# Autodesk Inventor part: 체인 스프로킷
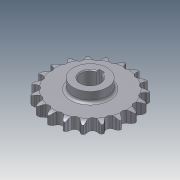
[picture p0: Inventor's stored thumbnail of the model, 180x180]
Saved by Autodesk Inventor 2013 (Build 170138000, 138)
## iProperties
Created: 2013-01
Part Number: 체인 스프로킷
Material: 강
Document SubType Name: Modeling
Designer: KYOUNG IL JANG
Density: 1 g/cm^3
CustomPartVersion: 1
Company: 한국ATC센터
Author: KYOUNG IL JANG
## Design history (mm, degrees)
sketch "이론적 톱니 프로파일"
  geometry: L1 (0, 0)-(0, 45.567); L2 (0, 0)-(14.795, 43.098); L3 (0, 45.567)-(14.795, 43.098); L4 (0, 45.567)-(5.661, 50.015); L5 (5.661, 50.015)-(-5.141, 45.406); L6 (-12.428, 43.493)-(-5.573, 46.417); L7 (-5.141, 45.406)-(-5.573, 46.417); L8 (5.573, 46.417)-(5.141, 45.406); L9 (0, 0)-(8.138, 48.771); A1 r 45.567 centre (0, 0) between (0, 45.567) and (14.795, 43.098); A2 r 49.445 centre (0, 0) between (7.302, 48.903) and (-7.302, 48.903); A3 r 4.545 centre (0, 45.567) between (-3.574, 42.758) and (3.574, 42.758); A4 r 7.453 centre (12.428, 43.493) between (7.302, 48.903) and (5.573, 46.417); A5 r 7.453 centre (-12.428, 43.493) between (-5.573, 46.417) and (-7.302, 48.903); A6 r 11.745 centre (5.661, 50.015) between (-5.141, 45.406) and (-3.574, 42.758); A7 r 11.745 centre (-5.661, 50.015) between (3.574, 42.758) and (5.141, 45.406); 2 further points
  constraints: 18 end point, 15 point on circle, 7 centre point, 3 coincident, 3 point on line, 3 symmetric about line, 3 tangent, 1 equal radius, 1 midpoint, 1 parallel, 1 vertical, 1 other
  dimensions: "d0" = 91.13301 diameter of A1 (computed from da_p, da_z); "d2" = 18.9474 deg angle of L2 L1 (computed from da_z); "d3" = 4.545 radius of A3 (= 0.5 x da_Dr + da_SC); "d10" = 128.158 deg angle of L4 L1 (computed from da_z); "d11" = 15.0526 deg angle of L5 L4 (computed from da_z); "d12" = 7.2 distance of L3.start L4.end (= 0.8 x da_Dr); "d13" = 11.745 distance of L4.end L5.end (= 1.3 x da_Dr + da_SC); "d14" = 12.6 distance of A4.centre L1.end (= 1.4 x da_Dr); "d23" = 4.5 distance from line of L9.end L3 (= da_Ha)
sketch "톱니 프로파일"
  geometry: L1 (0, 0)-(0, 45.567); L2 (0, 45.567)-(4.203, 43.837); L3 (0, 45.567)-(-4.203, 43.837); A1 r 4.545 centre (0, 45.567) between (-4.203, 43.837) and (4.203, 43.837); A2 r 22.68 centre (25.176, 35.206) between (7.12, 48.93) and (4.203, 43.837); A3 r 22.68 centre (-25.176, 35.206) between (-4.203, 43.837) and (-7.12, 48.93); A4 r 49.445 centre (0, 0) between (-7.12, 48.93) and (7.12, 48.93) reference; 1 further point
  constraints: 9 point on circle, 6 end point, 3 centre point, 2 tangent, 1 coincident, 1 equal radius, 1 vertical, 1 other
  dimensions: "d44" = 135.263 deg angle of L3 L2 (= da_Alfa); "d45" = 22.68 radius of A2 (= da_Re); "d46" = 4.545 radius of A1 (= da_Ri)
sketch "단면 프로파일"
  geometry: L1 (49.445, 0)-(-49.445, 0) reference; L2 (33.265, 6.65)-(-33.265, 6.65); L3 (-33.265, 6.65)-(-33.265, -6.65); L4 (-33.265, -6.65)-(33.265, -6.65); L5 (33.265, -6.65)-(33.265, 6.65); L6 (33.265, 6.65)-(49.445, 6.65); L7 (49.445, 6.65)-(49.445, -6.65); L8 (49.445, -6.65)-(33.265, -6.65); L9 (33.265, -6.65)-(33.265, 6.65); L10 (42.183, 6.65)-(0, 6.65); L11 (0, 6.65)-(0, -6.65); L12 (0, -6.65)-(42.183, -6.65); L13 (0, 6.65)-(0, -6.65); L14 (49.445, 4.775)-(49.445, -4.775); A1 r 15 centre (42.183, -8.35) between (49.445, 4.775) and (42.183, 6.65); A2 r 15 centre (42.183, 8.35) between (42.183, -6.65) and (49.445, -4.775); 2 further points
  constraints: 26 end point, 7 midpoint, 5 perpendicular, 4 parallel, 4 point on circle, 3 point on line, 3 symmetric about line, 2 centre point, 2 horizontal, 2 tangent, 1 collinear, 1 other
  dimensions: "d30" = 13.3 distance between parallel lines of L8 L6 (= da_Bf); "d31" = 66.53007 distance between parallel lines of L3 L5 (= da_Ds); "d32" = 13.3 distance between parallel lines of L4 L2 (= da_Bs); "d33" = 1.875 distance from line of L14.start L6 (= da_Ba); "d34" = 15 radius of A1 (= da_Rx); "d43" = 6.65 distance between parallel lines of L4 L1 (computed from da_k, da_pt, da_Bs)
revolve "슈라우드" stored, may be unused: angle "d36" = 90 deg
revolve "스트랜드" stored, may be unused: angle "d37" = 90 deg
extrude "이론적 톱니" cut sketch "이론적 톱니 프로파일" stored distance "d18" = 10; taper "d19" = 0 deg; dims "d49" = 0, "form_type" = 0 [user parameter]
extrude "톱니" cut sketch "톱니 프로파일" stored distance "d47" = 10; taper "d48" = 0 deg; dims "d50" = 10, "form_type" = 0 [user parameter]
node "타이밍 평면"
node "작업 평면3"
sketch "스케치5"
  geometry: C1 r 20 at (0, -45.567); 1 further point
  constraints: 1 centre point, 1 coincident
  dimensions: "d52" = 40 diameter of C1
extrude "돌출4" join sketch "스케치5" stored distance "d53" = 10; taper "d54" = 0 deg
sketch "스케치6"
  geometry: L1 (3, 10.583)-(3, 13.8); L2 (3, 13.8)-(-3, 13.8); L3 (-3, 13.8)-(-3, 10.583); A1 r 11 centre (0, 0) between (3, 10.583) and (-3, 10.583); 1 further point
  constraints: 6 end point, 2 parallel, 2 point on circle, 1 centre point, 1 coincident, 1 perpendicular, 1 vertical
  dimensions: "d55" = 22 diameter of A1; "d56" = 24.8 dimension on A1 L2 (computed from d55); "d57" = 6 distance of L1.end L2.end
extrude "돌출5" cut sketch "스케치6" stored distance "d58" = 10; taper "d59" = 0 deg
fillet "모깎기2" dims "d60" = 3
chamfer "모따기1" distance "d61" = 1; stored, may be unused: second distance "d62" = 2, angle "d63" = 45 deg
body "Solid1"
pattern_linear "스트랜드 패턴" dims "d40" = 24 (= da_pt)
pattern_circular "톱니 패턴" dims angle "d21" = 360 deg
other parameters: "da_p" = 15 [user parameter; used in 1 equation term], "da_Dr" = 9 [user parameter; used in 4 equation terms], "da_SC" = 0.045 [user parameter; used in 2 equation terms], "da_Ha" = 4.5 [user parameter; used in 1 equation term], "da_pt" = 24 [user parameter; used in 2 equation terms], "da_Bf" = 13.3 [user parameter; used in 1 equation term], "d28" = 0, "d29" = 0, "da_Ba" = 1.875 [user parameter; used in 1 equation term], "da_Rx" = 15 [user parameter; used in 1 equation term], "da_Ra" = 0.6 [user parameter], "da_Bs" = 13.3 [user parameter; used in 2 equation terms], "da_Ds" = 66.53007 [user parameter; used in 1 equation term], "d42" = 0, "da_Re" = 22.68 [user parameter; used in 1 equation term], "da_Ri" = 4.545 [user parameter; used in 1 equation term], "da_Alfa" = 135.263 deg [user parameter; used in 1 equation term], "d51" = -25
